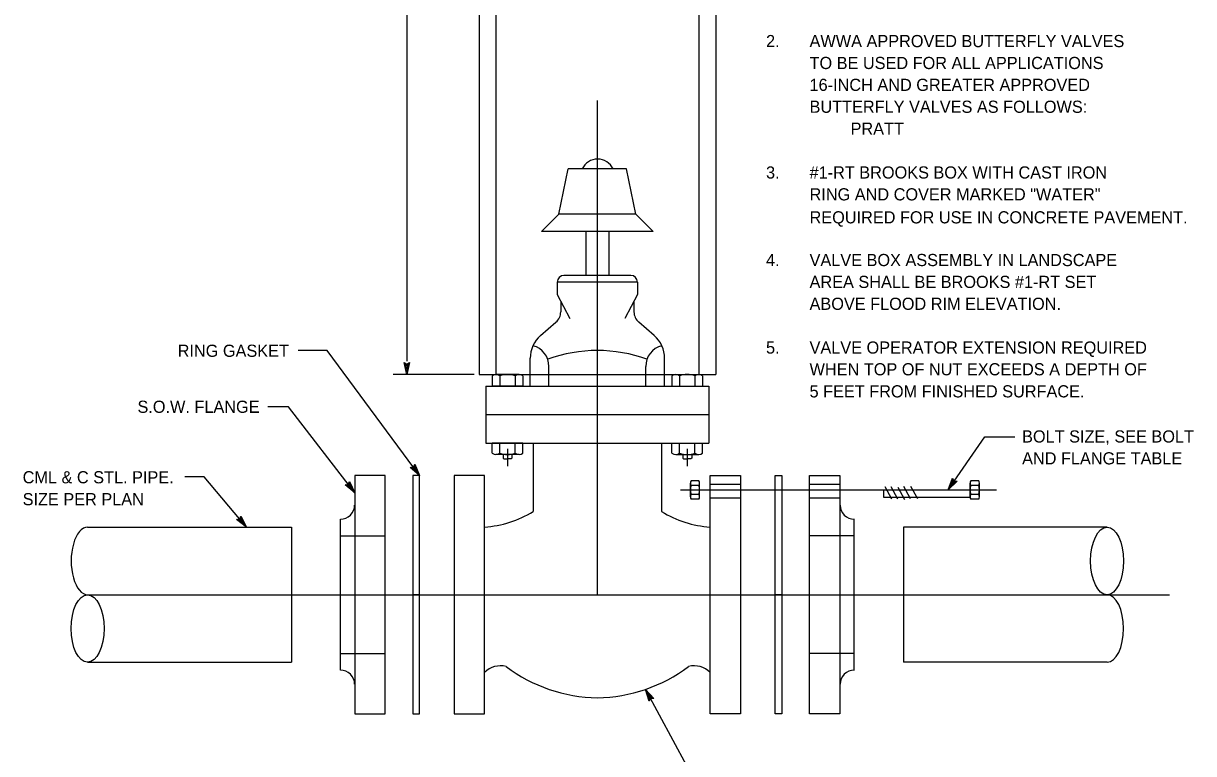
# Model space of a CAD drawing. Extents: x -121875 to -117742, y -103854 to -101122.
# Drawn here: x -121823 to -121246, y -101904 to -101544 of the extents above; entities that cross this region are included whole.
import ezdxf

# ---------------------------------------------------------------- set-up
doc = ezdxf.new("R2010")
doc.units = 0
for name, color, linetype in [('G-MARK', 7, 'Continuous'), ('G-TEXT', 7, 'Continuous'), ('Misc CnstDet(22)', 7, 'Continuous')]:
    doc.layers.add(name, color=color, linetype=linetype)

msp = doc.modelspace()

# ---------------------------------------------------------------- linework, layer by layer
at = {"layer": 'G-MARK'}
for p, q in [((-121633.54, -101349.26), (-121633.54, -101710.92)), ((-121600.25, -101717.59), (-121640.21, -101717.59))]:
    msp.add_line(p, q, dxfattribs=at)
for points in [[(-121627.19, -101767.38), (-121672.71, -101705.72), (-121687.09, -101705.72)], [(-121659.17, -101775.92), (-121691.88, -101733.42), (-121702.09, -101733.42)], [(-121366.67, -101774.47), (-121348.54, -101748.22), (-121333.75, -101748.22)], [(-121712.5, -101792.8), (-121733.34, -101768.01), (-121742.92, -101768.01)], [(-121515.87, -101872.82), (-121495.63, -101910.3), (-121482.92, -101910.3)]]:
    msp.add_lwpolyline(points, dxfattribs=at)
at = {"layer": 'G-TEXT'}
for p, q in [((-121633.54, -101717.59), (-121634.87, -101711.59)), ((-121634.87, -101711.59), (-121634.87, -101711.59)), ((-121634.87, -101711.59), (-121633.54, -101712.39)), ((-121633.55, -101716.2), (-121634.51, -101711.83)), ((-121633.54, -101714.83), (-121634.17, -101712)), ((-121633.54, -101712.39), (-121632.2, -101711.59)), ((-121632.2, -101711.59), (-121633.54, -101717.59)), ((-121632.56, -101711.81), (-121633.54, -101716.21)), ((-121632.2, -101711.59), (-121632.2, -101711.59)), ((-121633.54, -101713.45), (-121633.81, -101712.24)), ((-121632.92, -101712.04), (-121633.54, -101714.83)), ((-121633.27, -101712.22), (-121633.54, -101713.45)), ((-121633.54, -101717.59), (-121633.54, -101717.59)), ((-121631.8, -101763.32), (-121630.25, -101763.18)), ((-121627.19, -101767.38), (-121631.8, -101763.32)), ((-121631.8, -101763.32), (-121631.8, -101763.32)), ((-121628.01, -101766.26), (-121631.37, -101763.3)), ((-121628.82, -101765.15), (-121630.99, -101763.24)), ((-121629.63, -101764.03), (-121630.56, -101763.21)), ((-121630.25, -101763.18), (-121629.64, -101761.75)), ((-121630.13, -101762.88), (-121629.63, -101764.03)), ((-121629.95, -101762.53), (-121628.82, -101765.15)), ((-121629.8, -101762.13), (-121628, -101766.27)), ((-121629.64, -101761.75), (-121629.64, -101761.75)), ((-121629.64, -101761.75), (-121627.19, -101767.38)), ((-121627.19, -101767.38), (-121627.19, -101767.38)), ((-121366.67, -101774.47), (-121364.45, -101768.73)), ((-121365.9, -101773.31), (-121364.28, -101769.13)), ((-121365.14, -101772.17), (-121364.09, -101769.47)), ((-121364.45, -101768.74), (-121364.45, -101768.74)), ((-121364.45, -101768.74), (-121363.79, -101770.14)), ((-121663.9, -101772.01), (-121662.36, -101771.82)), ((-121659.17, -101775.92), (-121663.9, -101772.01)), ((-121663.9, -101772.01), (-121663.9, -101772.01)), ((-121660.03, -101774.83), (-121663.48, -101771.97)), ((-121660.86, -101773.74), (-121663.09, -101771.9)), ((-121661.71, -101772.65), (-121662.67, -101771.86)), ((-121662.36, -101771.82), (-121661.8, -101770.37)), ((-121662.25, -101771.51), (-121661.71, -101772.65)), ((-121662.09, -101771.16), (-121660.86, -101773.74)), ((-121661.95, -101770.76), (-121660.02, -101774.84)), ((-121661.8, -101770.37), (-121661.8, -101770.37)), ((-121661.8, -101770.37), (-121659.17, -101775.92)), ((-121362.23, -101770.21), (-121366.67, -101774.47)), ((-121366.67, -101774.47), (-121366.67, -101774.47)), ((-121362.64, -101770.2), (-121365.9, -101773.32)), ((-121363.07, -101770.19), (-121365.14, -101772.17)), ((-121364.37, -101771.02), (-121363.92, -101769.86)), ((-121363.46, -101770.15), (-121364.37, -101771.02)), ((-121363.79, -101770.14), (-121362.23, -101770.21)), ((-121362.23, -101770.21), (-121362.23, -101770.21)), ((-121659.17, -101775.92), (-121659.17, -101775.92)), ((-121717.39, -101789.07), (-121715.86, -101788.83)), ((-121712.5, -101792.8), (-121717.39, -101789.07)), ((-121717.39, -101789.07), (-121717.39, -101789.07)), ((-121713.4, -101791.74), (-121716.96, -101789.02)), ((-121714.28, -101790.69), (-121716.58, -101788.93)), ((-121715.17, -101789.63), (-121716.16, -101788.88)), ((-121715.86, -101788.83), (-121715.35, -101787.35)), ((-121715.76, -101788.51), (-121715.17, -101789.63)), ((-121715.61, -101788.16), (-121714.28, -101790.69)), ((-121715.48, -101787.75), (-121713.39, -101791.75)), ((-121715.35, -101787.35), (-121715.35, -101787.35)), ((-121715.35, -101787.35), (-121712.5, -101792.8)), ((-121712.5, -101792.8), (-121712.5, -101792.8)), ((-121514.1, -101878.7), (-121515.87, -101872.82)), ((-121515.87, -101872.82), (-121515.87, -101872.82)), ((-121515.87, -101872.82), (-121511.77, -101877.4)), ((-121513.89, -101878.34), (-121515.19, -101874.02)), ((-121515.18, -101874.03), (-121512.2, -101877.37)), ((-121513.69, -101877.96), (-121514.52, -101875.23)), ((-121514.52, -101875.23), (-121512.59, -101877.38)), ((-121513.32, -101877.35), (-121514.1, -101878.7)), ((-121514.1, -101878.7), (-121514.1, -101878.7)), ((-121513.48, -101877.64), (-121513.84, -101876.43)), ((-121513.84, -101876.43), (-121513.01, -101877.35)), ((-121511.77, -101877.4), (-121513.32, -101877.35)), ((-121511.77, -101877.4), (-121511.77, -101877.4))]:
    msp.add_line(p, q, dxfattribs=at)
at = {"layer": 'Misc CnstDet(22)'}
for p, q in [((-121597.92, -101342.59), (-121597.92, -101717.59)), ((-121481.25, -101342.59), (-121481.25, -101717.59)), ((-121589.59, -101380.3), (-121589.59, -101717.59)), ((-121489.59, -101380.3), (-121489.59, -101717.59)), ((-121539.59, -101826.13), (-121539.59, -101582.38)), ((-121558.54, -101638.42), (-121553.96, -101616.13)), ((-121525.21, -101616.13), (-121553.96, -101616.13)), ((-121520.63, -101638.42), (-121525.21, -101616.13)), ((-121558.54, -101638.42), (-121567.09, -101646.97)), ((-121520.63, -101638.42), (-121558.54, -101638.42)), ((-121520.63, -101638.42), (-121512.09, -101646.97)), ((-121512.09, -101646.97), (-121567.09, -101646.97)), ((-121545.21, -101646.97), (-121545.21, -101668.63)), ((-121533.96, -101646.97), (-121533.96, -101668.63)), ((-121523.13, -101668.63), (-121556.04, -101668.63)), ((-121519.79, -101671.97), (-121559.38, -101671.97)), ((-121559.38, -101671.97), (-121559.38, -101678.01)), ((-121519.79, -101671.97), (-121519.79, -101678.01)), ((-121559.38, -101678.01), (-121553.13, -101689.88)), ((-121557.64, -101681.31), (-121557.64, -101686.65)), ((-121519.79, -101678.01), (-121526.04, -101689.88)), ((-121521.53, -101681.31), (-121521.53, -101686.65)), ((-121567.58, -101698.34), (-121559.99, -101691.79)), ((-121511.59, -101698.34), (-121519.18, -101691.79)), ((-121572.71, -101723.22), (-121572.71, -101709.55)), ((-121506.46, -101723.22), (-121506.46, -101709.55)), ((-121597.92, -101717.59), (-121481.25, -101717.59)), ((-121578.19, -101717.58), (-121589.56, -101717.58)), ((-121500.98, -101717.58), (-121489.61, -101717.58)), ((-121594.59, -101723.22), (-121484.59, -101723.22)), ((-121594.59, -101723.22), (-121594.59, -101751.34)), ((-121591.45, -101718.14), (-121591.45, -101723.21)), ((-121576.3, -101723.21), (-121591.45, -101723.21)), ((-121587.66, -101718.14), (-121587.66, -101723.21)), ((-121580.09, -101718.14), (-121580.09, -101723.21)), ((-121576.3, -101718.14), (-121576.3, -101723.21)), ((-121502.87, -101718.14), (-121502.87, -101723.21)), ((-121502.87, -101723.21), (-121487.72, -101723.21)), ((-121499.08, -101718.14), (-121499.08, -101723.21)), ((-121491.5, -101718.14), (-121491.5, -101723.21)), ((-121487.72, -101718.14), (-121487.72, -101723.21)), ((-121484.59, -101723.22), (-121484.59, -101751.34)), ((-121594.59, -101737.28), (-121484.59, -101737.28)), ((-121594.59, -101751.34), (-121484.59, -101751.34)), ((-121576.3, -101751.33), (-121591.45, -101751.33)), ((-121591.45, -101756.39), (-121591.45, -101751.33)), ((-121587.66, -101756.39), (-121587.66, -101751.33)), ((-121580.09, -101756.39), (-121580.09, -101751.33)), ((-121576.3, -101756.39), (-121576.3, -101751.33)), ((-121571.25, -101751.34), (-121571.25, -101785.09)), ((-121507.92, -101751.34), (-121507.92, -101785.09)), ((-121502.87, -101751.33), (-121487.72, -101751.33)), ((-121502.87, -101756.39), (-121502.87, -101751.33)), ((-121499.08, -101756.39), (-121499.08, -101751.33)), ((-121491.5, -101756.39), (-121491.5, -101751.33)), ((-121487.72, -101756.39), (-121487.72, -101751.33)), ((-121578.19, -101756.95), (-121589.56, -101756.95)), ((-121583.88, -101754.26), (-121583.88, -101762.8)), ((-121500.98, -101756.95), (-121489.61, -101756.95)), ((-121495.29, -101754.26), (-121495.29, -101762.8)), ((-121498.54, -101774.47), (-121342.92, -101774.47)), ((-121493.73, -101777.88), (-121493.73, -101771.06)), ((-121489.49, -101769.92), (-121493.4, -101769.92)), ((-121489.49, -101772.2), (-121493.4, -101772.2)), ((-121489.16, -101777.88), (-121489.16, -101771.06)), ((-121483.96, -101771.55), (-121468.96, -101771.55)), ((-121435, -101771.55), (-121420, -101771.55)), ((-121398.54, -101774.47), (-121398.54, -101778.01)), ((-121397.92, -101772.8), (-121394.59, -101778.84)), ((-121394.99, -101772.85), (-121391.65, -101778.89)), ((-121391.45, -101773.06), (-121388.11, -101779.1)), ((-121388.74, -101772.64), (-121385.4, -101778.68)), ((-121385.2, -101772.64), (-121381.86, -101778.68)), ((-121355.84, -101777.88), (-121355.84, -101771.06)), ((-121351.6, -101769.92), (-121355.51, -101769.92)), ((-121351.6, -101772.2), (-121355.51, -101772.2)), ((-121351.26, -101777.88), (-121351.26, -101771.06)), ((-121489.49, -101776.74), (-121493.4, -101776.74)), ((-121489.49, -101779.02), (-121493.4, -101779.02)), ((-121483.96, -101778.42), (-121468.96, -101778.42)), ((-121435, -101778.42), (-121420, -101778.42)), ((-121398.54, -101778.01), (-121355.83, -101778.01)), ((-121351.6, -101776.74), (-121355.51, -101776.74)), ((-121351.6, -101779.02), (-121355.51, -101779.02)), ((-121666.25, -101863.42), (-121666.25, -101788.85)), ((-121412.92, -101863.42), (-121412.92, -101788.85)), ((-121790.84, -101792.8), (-121690.42, -101792.8)), ((-121690.42, -101792.8), (-121690.42, -101859.47)), ((-121666.25, -101797.17), (-121644.17, -101797.17)), ((-121412.92, -101797.17), (-121435, -101797.17)), ((-121288.34, -101792.8), (-121388.75, -101792.8)), ((-121388.75, -101792.8), (-121388.75, -101859.47)), ((-121790.84, -101826.13), (-121257.5, -101826.13)), ((-121666.25, -101855.09), (-121644.17, -101855.09)), ((-121412.92, -101855.09), (-121435, -101855.09)), ((-121790.84, -101859.47), (-121690.42, -101859.47)), ((-121288.34, -101859.47), (-121388.75, -101859.47))]:
    msp.add_line(p, q, dxfattribs=at)
for points in [[(-121563.54, -101723.22), (-121563.54, -101713.63)], [(-121515.63, -101723.22), (-121515.63, -101713.63)], [(-121586.1, -101756.97), (-121586.1, -101758.84), (-121585.68, -101759.05), (-121583.88, -101759.05)], [(-121581.67, -101756.97), (-121581.67, -101758.84), (-121582.09, -101759.05), (-121583.88, -101759.05)], [(-121497.5, -101756.97), (-121497.5, -101758.84), (-121497.09, -101759.05), (-121495.29, -101759.05)], [(-121493.07, -101756.97), (-121493.07, -101758.84), (-121493.49, -101759.05), (-121495.29, -101759.05)], [(-121630.52, -101767.38), (-121630.52, -101826.13), (-121627.19, -101826.13), (-121627.19, -101767.38), (-121630.52, -101767.38)], [(-121448.65, -101767.38), (-121448.65, -101826.13), (-121451.98, -101826.13), (-121451.98, -101767.38), (-121448.65, -101767.38)], [(-121627.19, -101884.88), (-121627.19, -101826.13), (-121630.52, -101826.13), (-121630.52, -101884.88), (-121627.19, -101884.88)], [(-121451.98, -101884.88), (-121451.98, -101826.13), (-121448.65, -101826.13), (-121448.65, -101884.88), (-121451.98, -101884.88)]]:
    msp.add_lwpolyline(points, dxfattribs=at)
for points in [[(-121659.17, -101884.88), (-121644.17, -101884.88), (-121644.17, -101767.38), (-121659.17, -101767.38)], [(-121627.19, -101884.88), (-121627.19, -101767.38), (-121630.52, -101767.38), (-121630.52, -101884.88)], [(-121610.21, -101884.88), (-121595.21, -101884.88), (-121595.21, -101767.38), (-121610.21, -101767.38)], [(-121468.96, -101884.88), (-121483.96, -101884.88), (-121483.96, -101767.38), (-121468.96, -101767.38)], [(-121451.98, -101884.88), (-121451.98, -101767.38), (-121448.65, -101767.38), (-121448.65, -101884.88)], [(-121420, -101884.88), (-121435, -101884.88), (-121435, -101767.38), (-121420, -101767.38)]]:
    msp.add_lwpolyline(points, close=True, dxfattribs=at)
for centre, radius, start, end in [((-121539.48, -101619.65), 8.38, 24.82016, 155.17984), ((-121556.04, -101671.97), 3.33, 90, 180), ((-121523.13, -101671.97), 3.33, 0, 90), ((-121564.43, -101686.65), 6.79, 310.81508, 0), ((-121514.74, -101686.65), 6.79, 180, 229.18492), ((-121557.89, -101709.55), 14.82, 130.81508, 180), ((-121521.28, -101709.55), 14.82, 0, 49.18492), ((-121573.65, -101713.24), 10.11, 357.75398, 76.96357), ((-121539.59, -101776.37), 70.69, 69.75171, 110.24829), ((-121505.52, -101713.24), 10.11, 103.03643, 182.24602), ((-121589.56, -101721.07), 3.49, 57.13278, 122.86722), ((-121583.88, -101730.7), 13.12, 73.22135, 106.77865), ((-121578.19, -101721.07), 3.49, 57.13278, 122.86722), ((-121500.98, -101721.07), 3.49, 57.13278, 122.86722), ((-121495.29, -101730.7), 13.12, 73.22135, 106.77865), ((-121489.61, -101721.07), 3.49, 57.13278, 122.86722), ((-121589.56, -101753.46), 3.49, 237.13278, 302.86722), ((-121583.88, -101743.83), 13.12, 253.22135, 286.77865), ((-121578.19, -101753.46), 3.49, 237.13278, 302.86722), ((-121500.98, -101753.46), 3.49, 237.13278, 302.86722), ((-121495.29, -101743.83), 13.12, 253.22135, 286.77865), ((-121489.61, -101753.46), 3.49, 237.13278, 302.86722), ((-121491.64, -101771.06), 2.09, 147.13278, 212.86722), ((-121485.86, -101774.47), 7.87, 163.22135, 196.77865), ((-121491.25, -101771.06), 2.09, 327.13278, 32.86722), ((-121497.03, -101774.47), 7.87, 343.22135, 16.77865), ((-121353.75, -101771.06), 2.09, 147.13278, 212.86722), ((-121347.97, -101774.47), 7.87, 163.22135, 196.77865), ((-121353.36, -101771.06), 2.09, 327.13278, 32.86722), ((-121359.14, -101774.47), 7.87, 343.22135, 16.77865), ((-121491.64, -101777.88), 2.09, 147.13278, 212.86722), ((-121491.25, -101777.88), 2.09, 327.13278, 32.86722), ((-121353.75, -101777.88), 2.09, 147.13278, 212.86722), ((-121353.36, -101777.88), 2.09, 327.13278, 32.86722), ((-121666.13, -101781.95), 6.9, 268.95807, 0), ((-121598.93, -101740.15), 52.78, 274.04121, 301.62882), ((-121480.24, -101740.15), 52.78, 238.37118, 265.95879), ((-121413.04, -101781.95), 6.9, 180, 271.04193), ((-121587.29, -101872.49), 11.28, 76.10131, 134.59896), ((-121538.23, -101799.73), 77.27, 233.13541, 268.99579), ((-121540.94, -101799.73), 77.27, 271.00421, 306.86459), ((-121491.88, -101872.49), 11.28, 45.40104, 103.89869), ((-121666.13, -101870.32), 6.9, 0, 91.04193), ((-121413.04, -101870.32), 6.9, 88.95807, 180)]:
    msp.add_arc(centre, radius, start, end, dxfattribs=at)
for centre, start_param, end_param in [((-121790.84, -101809.47), 0, 3.141593), ((-121288.34, -101842.8), 3.141593, 6.283185)]:
    msp.add_ellipse(centre, major_axis=(0, 16.67), ratio=0.4875, start_param=start_param, end_param=end_param, dxfattribs=at)
for centre in [(-121288.34, -101809.47), (-121790.84, -101842.8)]:
    msp.add_ellipse(centre, major_axis=(0, 16.67), ratio=0.4875, dxfattribs=at)

# ---------------------------------------------------------------- texts
for s, p in [('2.', (-121456.45, -101556.09)), ('AWWA APPROVED BUTTERFLY VALVES', (-121434.99, -101556.09)), ('TO BE USED FOR ALL APPLICATIONS', (-121434.99, -101566.89)), ('16-INCH AND GREATER APPROVED', (-121434.99, -101577.68)), ('BUTTERFLY VALVES AS FOLLOWS:', (-121434.99, -101588.48)), ('PRATT', (-121414.78, -101599.27)), ('3.', (-121456.45, -101620.89)), ('#1-RT BROOKS BOX WITH CAST IRON', (-121434.99, -101620.89)), ('RING AND COVER MARKED "WATER"', (-121434.99, -101631.68)), ('REQUIRED FOR USE IN CONCRETE PAVEMENT.', (-121434.99, -101643.02)), ('4.', (-121456.45, -101664.07)), ('VALVE BOX ASSEMBLY IN LANDSCAPE', (-121434.99, -101664.07)), ('AREA SHALL BE BROOKS #1-RT SET', (-121434.99, -101674.86)), ('ABOVE FLOOD RIM ELEVATION.', (-121434.99, -101685.65)), ('RING GASKET', (-121746.46, -101708.82)), ('5.', (-121456.45, -101707.24)), ('VALVE OPERATOR EXTENSION REQUIRED', (-121434.99, -101707.24)), ('WHEN TOP OF NUT EXCEEDS A DEPTH OF', (-121434.99, -101717.95)), ('5 FEET FROM FINISHED SURFACE.', (-121434.99, -101728.83)), ('S.O.W. FLANGE', (-121766.29, -101736.44)), ('BOLT SIZE, SEE BOLT', (-121330.22, -101751.08)), ('AND FLANGE TABLE', (-121330.22, -101761.87)), ('CML & C STL. PIPE.', (-121822.88, -101771.21)), ('SIZE PER PLAN', (-121822.88, -101782.01))]:
    msp.add_text(s, height=6, dxfattribs=at).set_placement(p)

doc.saveas('drawing.dxf')
